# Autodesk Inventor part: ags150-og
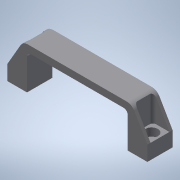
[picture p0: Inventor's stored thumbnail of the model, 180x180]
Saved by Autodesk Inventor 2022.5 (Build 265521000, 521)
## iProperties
Created: 2016-12
Part Number: ags150-og
Material: 一般
Document SubType Name: Modeling
Designer: imaocorp
Density: 1 g/cm^3
Appearance: 既定
Author: imaocorp
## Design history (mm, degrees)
node "ags150-og.x_t1"
node "ags150-og"
node "Base1"
